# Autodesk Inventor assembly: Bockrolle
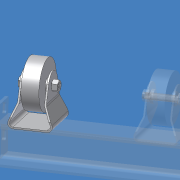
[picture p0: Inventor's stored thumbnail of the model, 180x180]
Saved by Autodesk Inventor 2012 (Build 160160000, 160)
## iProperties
Company: CAD-Verlag
Created: 2004-09
Part Number: Bockrolle
Document SubType Name: Assembly
Designer: Greiling
Manufacturer: Standard
Standards Organization: Custom
Control State: 0
Master: False
Checked Out: False
Shininess: 64.0
Length Units: 11269
Angle Units: 11279
Time Units: 11290
Mass Units: 11283
Length Display Precision: 3
Angle Display Precision: 2
Compacted: True
Density: 0.0
Volumn: 0.0
Area: 0.0
PropertySet Name: Model Information
Author: Jürgen Kronas
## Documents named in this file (5)
- C:\DemoDaten2012\CAD Daten\Daten Vault 2012 Inventor\Kapitel 6\6.4\Rollenbahn\Rollenbahn 1400\Bockrolle.iam
- C:\DemoDaten2012\CAD Daten\Daten Vault 2012 Inventor\Kapitel 6\6.4\Rollenbahn\Rollenbahn 1400\rollenträger.ipt
- C:\DemoDaten2012\CAD Daten\Daten Vault 2012 Inventor\Kapitel 6\6.4\Rollenbahn\Rollenbahn 1400\rolle150.ipt
- C:\DemoDaten2012\CAD Daten\Daten Vault 2012 Inventor\Kapitel 6\6.4\Rollenbahn\Bibliotheken\local.DIN.19.351.8.ipt
- C:\DemoDaten2012\CAD Daten\Daten Vault 2012 Inventor\Kapitel 6\6.4\Rollenbahn\Bibliotheken\local.AFNOR.63.150.8.ipt
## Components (4 placed, 4 different names)
1. rollenträger:1 — Passend:1, Passend:2, Einfügen:1, Einfügen:2
2. rolle150:1 — Passend:1, Passend:2
3. DIN 933  (Regelgewinde) - ersetzt durch DIN EN 24 017 M20  x 100:1 — Einfügen:1
4. NF EN 24032  (Regelgewinde) M20:1 — Einfügen:2
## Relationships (4: Mate 2, Insert 2)
- Passend:1 [Mate]: rollenträger:1 ↔ rolle150:1
- Passend:2 [Mate]: rollenträger:1 ↔ rolle150:1
- Einfügen:1 [Insert]: rollenträger:1 ↔ DIN 933  (Regelgewinde) - ersetzt durch DIN EN 24 017 M20  x 100:1
- Einfügen:2 [Insert]: rollenträger:1 ↔ NF EN 24032  (Regelgewinde) M20:1
